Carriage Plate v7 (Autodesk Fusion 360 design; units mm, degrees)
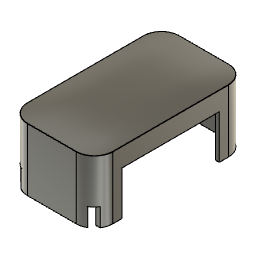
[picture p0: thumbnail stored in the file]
parameter "d34" = 2.5
sketch "Sketch1" plane through (0, 0, 0) normal (0, 0, 1) x axis (1, 0, 0)
  line L1 (-20, 57.5) -> (20, 57.5)
  line L2 (-30, -47.5) -> (-30, 47.5)
  line L3 (20, -57.5) -> (-20, -57.5)
  line L4 (30, 47.5) -> (30, -47.5)
  line L5 (0, 22.5) -> (0, 1.75)
  line L6 (22.5, 0) -> (1.75, 0)
  circle C1 centre (0, 47.5) radius 2.46
  circle C2 centre (20, -47.5) radius 2.46
  circle C3 centre (0, -47.5) radius 2.46
  circle C4 centre (-20, -47.5) radius 2.46
  circle C5 centre (20, 47.5) radius 2.46
  circle C6 centre (-20, 47.5) radius 2.46
  arc A1 centre (20, 47.5) radius 10 clockwise from (20, 57.5) to (30, 47.5)
  arc A2 centre (-20, 47.5) radius 10 clockwise from (-30, 47.5) to (-20, 57.5)
  arc A3 centre (-20, -47.5) radius 10 clockwise from (-20, -57.5) to (-30, -47.5)
  arc A4 centre (20, -47.5) radius 10 clockwise from (30, -47.5) to (20, -57.5)
  circle C7 centre (-15, -20) radius 2
  circle C8 centre (15, -20) radius 2
  circle C9 centre (-15, 20) radius 2
  circle C10 centre (15, 20) radius 2
  point P1 (0, 0)
  point P2 (0, 0)
  point P4 (20, -47.5)
  point P5 (0, -47.5)
  point P6 (-20, -47.5)
  point P3 (0, 47.5)
  point P7 (20, 47.5)
  point P8 (-20, 47.5)
  point P9 (0, 0)
  point P10 (20, 57.5)
  point P16 (-30, -47.5)
  point P22 (-30, -47.5)
  point P23 (20, 57.5)
  point P24 (-15, -20)
  coincident P1 P2
  horizontal P4 P5
  horizontal P5 P6
  equal C2 C3
  equal C3 C4
  equal C4 C6
  equal C1 C6
  equal C1 C5
  vertical P2 P3
  horizontal P3 P7
  horizontal P3 P8
  vertical P1 P5
  vertical P4 P7
  vertical P6 P8
  perpendicular L1 L2
  parallel L1 L3
  parallel L2 L4
  horizontal L1
  coincident P1 P9
  tangent L4 A1
  coincident L1 P10
  tangent L2 A2
  tangent L3 A3
  coincident L2 P16
  tangent L3 A4
  coincident A3 P22
  coincident A1 P23
  tangent L1 A2
  tangent L1 A1
  tangent L4 A4
  tangent L2 A3
  equal A3 A4
  equal A1 A4
  equal A1 A2
  symmetric C7 L5 C8
  symmetric C7 L6 C9
  symmetric C8 L6 C10
  dimension "d3" distance P2 P3 = 47.5 (= "( 95 / 2 ) * 1 mm")
  dimension "d4" distance P1 P5 = 47.5 (= "d3")
  dimension "d5" distance P4 P5 = 20
  dimension "d6" distance P5 P6 = 20 (= "d5")
  dimension "d7" diameter C1 = 4.92
  dimension "d8" distance P7 L1 = 10
  dimension "d9" distance P7 L4 = 10
  dimension "d10" distance P4 L3 = 10 (= "d8")
  dimension "d12" distance P6 L2 = 10 (= "d8")
  dimension "d13" radius A2 = 10
  dimension "d18" diameter C7 = 4
  dimension "d22" distance P9 P24 = 20
  dimension "d23" distance P2 P24 = 15
extrude "Extrude1" new body sketch "Sketch1" profile of C1 C2 C3 C4 C5 C6 L1 L2 L3 L4 A1 A2 A3 A4 C7 C8 C9 C10 along normal blind 5
work_plane "WorkPlane1" AlongDistance 0.25
sketch "Sketch2" plane through (0, 0, 5.25) normal (0, 0, 1) x axis (1, 0, 0)
  line L1 (30, 47.5) -> (30, -47.5)
  line L2 (-20, 57.5) -> (20, 57.5)
  line L3 (-30, -47.5) -> (-30, 47.5)
  line L4 (20, -57.5) -> (-20, -57.5)
  line L5 (20, -62.5) -> (-20, -62.5)
  line L6 (35, 47.5) -> (35, -47.5)
  line L7 (-20, 62.5) -> (20, 62.5)
  line L8 (-35, -47.5) -> (-35, 47.5)
  circle C1 centre (0, -47.5) radius 2.46
  circle C2 centre (0, 47.5) radius 2.46
  circle C3 centre (20, -47.5) radius 2.46
  circle C4 centre (-20, -47.5) radius 2.46
  circle C5 centre (15, 20) radius 2
  circle C6 centre (-15, -20) radius 2
  circle C7 centre (-20, 47.5) radius 2.46
  circle C8 centre (-15, 20) radius 2
  circle C9 centre (15, -20) radius 2
  circle C10 centre (20, 47.5) radius 2.46
  arc A1 centre (20, -47.5) radius 10 clockwise from (30, -47.5) to (20, -57.5)
  arc A2 centre (20, 47.5) radius 10 clockwise from (20, 57.5) to (30, 47.5)
  arc A3 centre (-20, 47.5) radius 10 clockwise from (-30, 47.5) to (-20, 57.5)
  arc A4 centre (-20, -47.5) radius 10 clockwise from (-20, -57.5) to (-30, -47.5)
  arc A5 centre (20, -47.5) radius 15 clockwise from (35, -47.5) to (20, -62.5)
  arc A6 centre (20, 47.5) radius 15 clockwise from (20, 62.5) to (35, 47.5)
  arc A7 centre (-20, 47.5) radius 15 clockwise from (-35, 47.5) to (-20, 62.5)
  arc A8 centre (-20, -47.5) radius 15 clockwise from (-20, -62.5) to (-35, -47.5)
  circle C11 centre (-15, 20) radius 2.15
  circle C12 centre (15, 20) radius 2.15
  circle C13 centre (15, -20) radius 2.15
  circle C14 centre (-15, -20) radius 2.15
  circle C15 centre (20, 47.5) radius 5.5
  circle C16 centre (0, 47.5) radius 5.5
  circle C17 centre (-20, 47.5) radius 5.5
  circle C18 centre (-20, -47.5) radius 5.5
  circle C19 centre (0, -47.5) radius 5.5
  circle C20 centre (20, -47.5) radius 5.5
  concentric C8 C11
  concentric C5 C12
  concentric C9 C13
  concentric C6 C14
  equal C13 C14
  equal C12 C13
  equal C11 C12
  concentric C10 C15
  concentric C2 C16
  concentric C7 C17
  concentric C4 C18
  concentric C1 C19
  concentric C3 C20
  equal C18 C19
  equal C19 C20
  equal C17 C20
  equal C16 C17
  equal C15 C16
  dimension "d31" = 5
  dimension "d53" diameter C11 = 4.3
  dimension "d56" diameter C15 = 11
extrude "Extrude2" new body sketch "Sketch2" profile of L5 A5 L6 A6 A7 L7 L8 A8 C11 C12 C13 C14 C15 C16 C17 C18 C19 C20 along normal blind 6
extrude "Extrude3" cut sketch "Sketch2" profile of C15 C16 C17 C18 C19 C20 along normal blind 4
extrude "Extrude6" cut sketch "Sketch2" profile of C11 C12 C13 C14 along normal blind 4.1
work_plane "WorkPlane2" AlongDistance 0
sketch "Sketch3" plane through (0, 0, 5.25) normal (0, 0, -1) x axis (1, 0, 0)
  line L1 (-35, -47.5) -> (-35, 47.5)
  line L2 (20, -62.5) -> (-20, -62.5)
  line L3 (35, 47.5) -> (35, -47.5)
  line L4 (-20, 62.5) -> (20, 62.5)
  line L5 (-32, -47.5) -> (-32, 47.5)
  line L6 (20, -59.5) -> (-20, -59.5)
  line L7 (32, 47.5) -> (32, -47.5)
  line L8 (-20, 59.5) -> (20, 59.5)
  arc A1 centre (-20, 47.5) radius 15 clockwise from (-35, 47.5) to (-20, 62.5)
  arc A2 centre (-20, -47.5) radius 15 clockwise from (-20, -62.5) to (-35, -47.5)
  arc A3 centre (20, -47.5) radius 15 clockwise from (35, -47.5) to (20, -62.5)
  arc A4 centre (20, 47.5) radius 15 clockwise from (20, 62.5) to (35, 47.5)
  arc A5 centre (-20, -47.5) radius 12 clockwise from (-20, -59.5) to (-32, -47.5)
  arc A6 centre (20, -47.5) radius 12 clockwise from (32, -47.5) to (20, -59.5)
  arc A7 centre (20, 47.5) radius 12 clockwise from (20, 59.5) to (32, 47.5)
  arc A8 centre (-20, 47.5) radius 12 clockwise from (-32, 47.5) to (-20, 59.5)
  circle C1 centre (15, -20) radius 2.15
  circle C2 centre (-15, 20) radius 2.15
  circle C3 centre (-15, -20) radius 2.15
  circle C4 centre (15, 20) radius 2.15
  circle C5 centre (0, -47.5) radius 5.5
  circle C6 centre (20, 47.5) radius 5.5
  circle C7 centre (-20, -47.5) radius 5.5
  circle C8 centre (-20, 47.5) radius 5.5
  circle C9 centre (0, 47.5) radius 5.5
  circle C10 centre (20, -47.5) radius 5.5
  dimension "d43" = -3
extrude "Extrude4" add sketch "Sketch3" profile of A1 L1 A2 L2 A3 L3 A4 L4 L5 A8 A5 L8 L6 L7 A6 A7 to an object offset 40
sketch "Sketch4" plane through (0, 0, 0) normal (1, 0, 0) x axis (0, 1, 0)
  line L1 (-47.5, -40) -> (-62.5, -40)
  line L2 (47.5, -40) -> (-47.5, -40)
  line L3 (62.5, -40) -> (47.5, -40)
  line L4 (-47.5, 11.25) -> (47.5, 11.25)
  line L5 (47.5, 11.25) -> (62.5, 11.25)
  line L6 (62.5, 11.25) -> (62.5, -40)
  line L7 (-62.5, 11.25) -> (-62.5, -40)
  line L8 (-62.5, 11.25) -> (-47.5, 11.25)
  line L9 (40, -4) -> (-40, -4)
  line L10 (40, -51.5126) -> (40, -4)
  line L11 (-40, -51.5126) -> (40, -51.5126)
  line L12 (-40, -4) -> (-40, -51.5126)
  line L13 (-57.5, 5) -> (-57.5, 0)
  line L14 (-57.5, 0) -> (-47.5, 0)
  line L15 (-57.5, 5) -> (-47.5, 5)
  line L16 (-47.5, 0) -> (47.5, 0)
  line L17 (-47.5, 5) -> (47.5, 5)
  line L18 (47.5, 0) -> (57.5, 0)
  line L19 (47.5, 5) -> (57.5, 5)
  line L20 (57.5, 5) -> (57.5, 0)
  line L21 (-55.5, -40) -> (-55.5, -25)
  line L22 (-60.5, -40) -> (-55.5, -40)
  line L23 (-60.5, -25) -> (-60.5, -40)
  line L24 (-55.5, -25) -> (-60.5, -25)
  point P10 (-40, -4)
  point P14 (-40, -4)
  point P23 (0, -4)
  point P1 (0, 0)
  point P28 (-58, -40)
  point P2 (-62.5, -40)
  perpendicular L3 L10
  perpendicular L10 L11
  perpendicular L11 L12
  coincident P10 P14
  midpoint L9 P23
  vertical P1 P23
  perpendicular L21 L22
  parallel L21 L23
  parallel L22 L24
  vertical L21
  midpoint L22 P28
  collinear L1 L22
  dimension "d47" distance L9 L17 = 9
  dimension "d48" distance L10 L12 = 80
  dimension "d59" distance L21 L23 = 5
  dimension "d61" distance L7 P28 = 4.5
  dimension "d62" distance P2 L24 = 15
extrude "Extrude5" cut sketch "Sketch4" profile of L9 L10 L11 L12 L21 L22 L23 L24 along normal blind 140 and against normal blind 145
chamfer "Chamfer1" distance 1
work_plane "WorkPlane3" PathDistance 0.8115
sketch "Sketch5" plane through (-35, -2.3885, 11.25) normal (0, -1, 0) x axis (1, 0, 0)
  curve K1 (34.4502, 6.6702) -> (0, 0)
  point P1 (0, 0)
  point P2 (0, 0)
  coincident P1 P2
form "Form4"
extrude "Extrude8" add of existing geometry to an object
fillet "Fillet3" ChordLen 0.25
